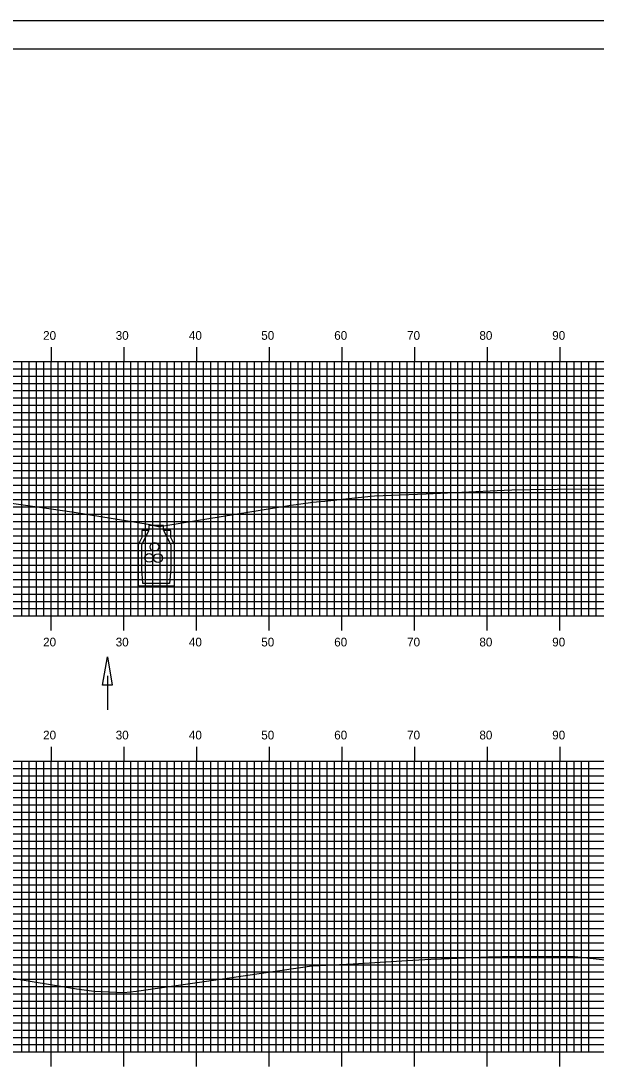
# Model space of a CAD drawing. Extents: x 852320 to 852663, y 366605 to 366825.
# Drawn here: x 852501.3 to 852580.5, y 366680.6 to 366824.9 of the extents above; entities that cross this region are included whole.
import ezdxf

# ---------------------------------------------------------------- set-up
doc = ezdxf.new("R2010")
doc.units = 0
for name, color, linetype in [('BORDER', 7, 'Continuous'), ('D_Drainage_Ditch_Line', 7, 'Continuous'), ('H_V ANNOTATION', 7, 'Continuous'), ('M_Drainage_CB', 7, 'Continuous'), ('M_Roadway_Centerline', 7, 'Continuous'), ('MAJOR', 7, 'Continuous'), ('MINOR', 7, 'Continuous'), ('PLOT BOUNDARY', 7, 'Continuous'), ('S_Drainage_CB', 7, 'Continuous'), ('S_Drainage_Invert', 7, 'Continuous'), ('S_Roadway_Centerline', 7, 'Continuous')]:
    doc.layers.add(name, color=color, linetype=linetype)

msp = doc.modelspace()

# ---------------------------------------------------------------- linework, layer by layer
at = {"layer": 'BORDER'}
msp.add_lwpolyline([(852335.88, 366611.06), (852655.88, 366611.06), (852655.88, 366821.06), (852335.88, 366821.06)], close=True, dxfattribs=at)
at = {"layer": 'D_Drainage_Ditch_Line'}
msp.add_line((852513.23, 366734.83), (852513.23, 366730.13), dxfattribs=at)
msp.add_lwpolyline([(852513.88, 366733.52), (852512.57, 366733.52), (852513.23, 366737.45)], close=True, dxfattribs=at)
at = {"layer": 'M_Drainage_CB'}
for p, q in [((852517.96, 366753.85), (852517.47, 366752.83)), ((852518.95, 366754.83), (852517.96, 366754.83)), ((852517.96, 366754.83), (852517.96, 366753.85)), ((852517.96, 366752.83), (852518.95, 366754.83)), ((852521.97, 366754.83), (852520.95, 366754.83)), ((852520.95, 366754.83), (852521.97, 366752.83)), ((852521.97, 366753.85), (852521.97, 366754.83)), ((852522.46, 366752.83), (852521.97, 366753.85)), ((852517.47, 366752.83), (852517.47, 366747.19)), ((852517.96, 366749.52), (852517.96, 366752.83)), ((852521.97, 366752.83), (852521.97, 366749.52)), ((852522.46, 366747.19), (852522.46, 366752.83)), ((852518.13, 366747.52), (852517.96, 366749.52)), ((852521.97, 366749.52), (852521.8, 366747.52)), ((852517.47, 366747.19), (852522.46, 366747.19)), ((852521.8, 366747.52), (852518.13, 366747.52))]:
    msp.add_line(p, q, dxfattribs=at)
msp.add_lwpolyline([(852521.44, 366754.87), (852520.95, 366754.87), (852520.95, 366755.5), (852518.95, 366755.5), (852518.95, 366754.87), (852518.46, 366754.87)], dxfattribs=at)
at = {"layer": 'MAJOR'}
for p, q in [((852505.48, 366780.06), (852505.48, 366778.06)), ((852515.48, 366780.06), (852515.48, 366778.06)), ((852525.48, 366780.06), (852525.48, 366778.06)), ((852535.48, 366780.06), (852535.48, 366778.06)), ((852545.48, 366780.06), (852545.48, 366778.06)), ((852555.48, 366780.06), (852555.48, 366778.06)), ((852565.48, 366780.06), (852565.48, 366778.06)), ((852575.48, 366780.06), (852575.48, 366778.06)), ((852345.48, 366778.06), (852625.48, 366778.06)), ((852345.48, 366778.06), (852625.48, 366778.06)), ((852505.48, 366743.06), (852505.48, 366778.06)), ((852515.48, 366743.06), (852515.48, 366778.06)), ((852525.48, 366743.06), (852525.48, 366778.06)), ((852535.48, 366743.06), (852535.48, 366778.06)), ((852545.48, 366743.06), (852545.48, 366778.06)), ((852555.48, 366743.06), (852555.48, 366778.06)), ((852565.48, 366743.06), (852565.48, 366778.06)), ((852575.48, 366743.06), (852575.48, 366778.06)), ((852345.48, 366773.06), (852625.48, 366773.06)), ((852345.48, 366768.06), (852625.48, 366768.06)), ((852345.48, 366763.06), (852625.48, 366763.06)), ((852345.48, 366758.06), (852625.48, 366758.06)), ((852345.48, 366753.06), (852625.48, 366753.06)), ((852345.48, 366748.06), (852625.48, 366748.06)), ((852345.48, 366743.06), (852625.48, 366743.06)), ((852345.48, 366743.06), (852625.48, 366743.06)), ((852505.48, 366741.05), (852505.48, 366743.06)), ((852515.48, 366741.05), (852515.48, 366743.06)), ((852525.48, 366741.05), (852525.48, 366743.06)), ((852535.48, 366741.05), (852535.48, 366743.06)), ((852545.48, 366741.05), (852545.48, 366743.06)), ((852555.48, 366741.05), (852555.48, 366743.06)), ((852565.48, 366741.05), (852565.48, 366743.06)), ((852575.48, 366741.05), (852575.48, 366743.06)), ((852505.48, 366725.06), (852505.48, 366723.06)), ((852515.48, 366725.06), (852515.48, 366723.06)), ((852525.48, 366725.06), (852525.48, 366723.06)), ((852535.48, 366725.06), (852535.48, 366723.06)), ((852545.48, 366725.06), (852545.48, 366723.06)), ((852555.48, 366725.06), (852555.48, 366723.06)), ((852565.48, 366725.06), (852565.48, 366723.06)), ((852575.48, 366725.06), (852575.48, 366723.06)), ((852345.48, 366723.06), (852625.48, 366723.06)), ((852345.48, 366723.06), (852625.48, 366723.06)), ((852505.48, 366683.06), (852505.48, 366723.06)), ((852515.48, 366683.06), (852515.48, 366723.06)), ((852525.48, 366683.06), (852525.48, 366723.06)), ((852535.48, 366683.06), (852535.48, 366723.06)), ((852545.48, 366683.06), (852545.48, 366723.06)), ((852555.48, 366683.06), (852555.48, 366723.06)), ((852565.48, 366683.06), (852565.48, 366723.06)), ((852575.48, 366683.06), (852575.48, 366723.06)), ((852345.48, 366718.06), (852625.48, 366718.06)), ((852345.48, 366713.06), (852625.48, 366713.06)), ((852345.48, 366708.06), (852625.48, 366708.06)), ((852345.48, 366703.06), (852625.48, 366703.06)), ((852345.48, 366698.06), (852625.48, 366698.06)), ((852345.48, 366693.06), (852625.48, 366693.06)), ((852345.48, 366688.06), (852625.48, 366688.06)), ((852345.48, 366683.06), (852625.48, 366683.06)), ((852345.48, 366683.06), (852625.48, 366683.06)), ((852505.48, 366681.05), (852505.48, 366683.06)), ((852515.48, 366681.05), (852515.48, 366683.06)), ((852525.48, 366681.05), (852525.48, 366683.06)), ((852535.48, 366681.05), (852535.48, 366683.06)), ((852545.48, 366681.05), (852545.48, 366683.06)), ((852555.48, 366681.05), (852555.48, 366683.06)), ((852565.48, 366681.05), (852565.48, 366683.06)), ((852575.48, 366681.05), (852575.48, 366683.06))]:
    msp.add_line(p, q, dxfattribs=at)
at = {"layer": 'MINOR'}
for p, q in [((852345.48, 366777.06), (852625.48, 366777.06)), ((852501.48, 366743.06), (852501.48, 366778.06)), ((852502.48, 366743.06), (852502.48, 366778.06)), ((852503.48, 366743.06), (852503.48, 366778.06)), ((852504.48, 366743.06), (852504.48, 366778.06)), ((852506.48, 366743.06), (852506.48, 366778.06)), ((852507.48, 366743.06), (852507.48, 366778.06)), ((852508.48, 366743.06), (852508.48, 366778.06)), ((852509.48, 366743.06), (852509.48, 366778.06)), ((852510.48, 366743.06), (852510.48, 366778.06)), ((852511.48, 366743.06), (852511.48, 366778.06)), ((852512.48, 366743.06), (852512.48, 366778.06)), ((852513.48, 366743.06), (852513.48, 366778.06)), ((852514.48, 366743.06), (852514.48, 366778.06)), ((852516.48, 366743.06), (852516.48, 366778.06)), ((852517.48, 366743.06), (852517.48, 366778.06)), ((852518.48, 366743.06), (852518.48, 366778.06)), ((852519.48, 366743.06), (852519.48, 366778.06)), ((852520.48, 366743.06), (852520.48, 366778.06)), ((852521.48, 366743.06), (852521.48, 366778.06)), ((852522.48, 366743.06), (852522.48, 366778.06)), ((852523.48, 366743.06), (852523.48, 366778.06)), ((852524.48, 366743.06), (852524.48, 366778.06)), ((852526.48, 366743.06), (852526.48, 366778.06)), ((852527.48, 366743.06), (852527.48, 366778.06)), ((852528.48, 366743.06), (852528.48, 366778.06)), ((852529.48, 366743.06), (852529.48, 366778.06)), ((852530.48, 366743.06), (852530.48, 366778.06)), ((852531.48, 366743.06), (852531.48, 366778.06)), ((852532.48, 366743.06), (852532.48, 366778.06)), ((852533.48, 366743.06), (852533.48, 366778.06)), ((852534.48, 366743.06), (852534.48, 366778.06)), ((852536.48, 366743.06), (852536.48, 366778.06)), ((852537.48, 366743.06), (852537.48, 366778.06)), ((852538.48, 366743.06), (852538.48, 366778.06)), ((852539.48, 366743.06), (852539.48, 366778.06)), ((852540.48, 366743.06), (852540.48, 366778.06)), ((852541.48, 366743.06), (852541.48, 366778.06)), ((852542.48, 366743.06), (852542.48, 366778.06)), ((852543.48, 366743.06), (852543.48, 366778.06)), ((852544.48, 366743.06), (852544.48, 366778.06)), ((852546.48, 366743.06), (852546.48, 366778.06)), ((852547.48, 366743.06), (852547.48, 366778.06)), ((852548.48, 366743.06), (852548.48, 366778.06)), ((852549.48, 366743.06), (852549.48, 366778.06)), ((852550.48, 366743.06), (852550.48, 366778.06)), ((852551.48, 366743.06), (852551.48, 366778.06)), ((852552.48, 366743.06), (852552.48, 366778.06)), ((852553.48, 366743.06), (852553.48, 366778.06)), ((852554.48, 366743.06), (852554.48, 366778.06)), ((852556.48, 366743.06), (852556.48, 366778.06)), ((852557.48, 366743.06), (852557.48, 366778.06)), ((852558.48, 366743.06), (852558.48, 366778.06)), ((852559.48, 366743.06), (852559.48, 366778.06)), ((852560.48, 366743.06), (852560.48, 366778.06)), ((852561.48, 366743.06), (852561.48, 366778.06)), ((852562.48, 366743.06), (852562.48, 366778.06)), ((852563.48, 366743.06), (852563.48, 366778.06)), ((852564.48, 366743.06), (852564.48, 366778.06)), ((852566.48, 366743.06), (852566.48, 366778.06)), ((852567.48, 366743.06), (852567.48, 366778.06)), ((852568.48, 366743.06), (852568.48, 366778.06)), ((852569.48, 366743.06), (852569.48, 366778.06)), ((852570.48, 366743.06), (852570.48, 366778.06)), ((852571.48, 366743.06), (852571.48, 366778.06)), ((852572.48, 366743.06), (852572.48, 366778.06)), ((852573.48, 366743.06), (852573.48, 366778.06)), ((852574.48, 366743.06), (852574.48, 366778.06)), ((852576.48, 366743.06), (852576.48, 366778.06)), ((852577.48, 366743.06), (852577.48, 366778.06)), ((852578.48, 366743.06), (852578.48, 366778.06)), ((852579.48, 366743.06), (852579.48, 366778.06)), ((852580.48, 366743.06), (852580.48, 366778.06)), ((852345.48, 366776.06), (852625.48, 366776.06)), ((852345.48, 366775.06), (852625.48, 366775.06)), ((852345.48, 366774.06), (852625.48, 366774.06)), ((852345.48, 366772.06), (852625.48, 366772.06)), ((852345.48, 366771.06), (852625.48, 366771.06)), ((852345.48, 366770.06), (852625.48, 366770.06)), ((852345.48, 366769.06), (852625.48, 366769.06)), ((852345.48, 366767.06), (852625.48, 366767.06)), ((852345.48, 366766.06), (852625.48, 366766.06)), ((852345.48, 366765.06), (852625.48, 366765.06)), ((852345.48, 366764.06), (852625.48, 366764.06)), ((852345.48, 366762.06), (852625.48, 366762.06)), ((852345.48, 366761.06), (852625.48, 366761.06)), ((852345.48, 366760.06), (852625.48, 366760.06)), ((852345.48, 366759.06), (852625.48, 366759.06)), ((852345.48, 366757.06), (852625.48, 366757.06)), ((852345.48, 366756.06), (852625.48, 366756.06)), ((852345.48, 366755.06), (852625.48, 366755.06)), ((852345.48, 366754.06), (852625.48, 366754.06)), ((852345.48, 366752.06), (852625.48, 366752.06)), ((852345.48, 366751.06), (852625.48, 366751.06)), ((852345.48, 366750.06), (852625.48, 366750.06)), ((852345.48, 366749.06), (852625.48, 366749.06)), ((852345.48, 366747.06), (852625.48, 366747.06)), ((852345.48, 366746.06), (852625.48, 366746.06)), ((852345.48, 366745.06), (852625.48, 366745.06)), ((852345.48, 366744.06), (852625.48, 366744.06)), ((852345.48, 366722.06), (852625.48, 366722.06)), ((852501.48, 366683.06), (852501.48, 366723.06)), ((852502.48, 366683.06), (852502.48, 366723.06)), ((852503.48, 366683.06), (852503.48, 366723.06)), ((852504.48, 366683.06), (852504.48, 366723.06)), ((852506.48, 366683.06), (852506.48, 366723.06)), ((852507.48, 366683.06), (852507.48, 366723.06)), ((852508.48, 366683.06), (852508.48, 366723.06)), ((852509.48, 366683.06), (852509.48, 366723.06)), ((852510.48, 366683.06), (852510.48, 366723.06)), ((852511.48, 366683.06), (852511.48, 366723.06)), ((852512.48, 366683.06), (852512.48, 366723.06)), ((852513.48, 366683.06), (852513.48, 366723.06)), ((852514.48, 366683.06), (852514.48, 366723.06)), ((852516.48, 366683.06), (852516.48, 366723.06)), ((852517.48, 366683.06), (852517.48, 366723.06)), ((852518.48, 366683.06), (852518.48, 366723.06)), ((852519.48, 366683.06), (852519.48, 366723.06)), ((852520.48, 366683.06), (852520.48, 366723.06)), ((852521.48, 366683.06), (852521.48, 366723.06)), ((852522.48, 366683.06), (852522.48, 366723.06)), ((852523.48, 366683.06), (852523.48, 366723.06)), ((852524.48, 366683.06), (852524.48, 366723.06)), ((852526.48, 366683.06), (852526.48, 366723.06)), ((852527.48, 366683.06), (852527.48, 366723.06)), ((852528.48, 366683.06), (852528.48, 366723.06)), ((852529.48, 366683.06), (852529.48, 366723.06)), ((852530.48, 366683.06), (852530.48, 366723.06)), ((852531.48, 366683.06), (852531.48, 366723.06)), ((852532.48, 366683.06), (852532.48, 366723.06)), ((852533.48, 366683.06), (852533.48, 366723.06)), ((852534.48, 366683.06), (852534.48, 366723.06)), ((852536.48, 366683.06), (852536.48, 366723.06)), ((852537.48, 366683.06), (852537.48, 366723.06)), ((852538.48, 366683.06), (852538.48, 366723.06)), ((852539.48, 366683.06), (852539.48, 366723.06)), ((852540.48, 366683.06), (852540.48, 366723.06)), ((852541.48, 366683.06), (852541.48, 366723.06)), ((852542.48, 366683.06), (852542.48, 366723.06)), ((852543.48, 366683.06), (852543.48, 366723.06)), ((852544.48, 366683.06), (852544.48, 366723.06)), ((852546.48, 366683.06), (852546.48, 366723.06)), ((852547.48, 366683.06), (852547.48, 366723.06)), ((852548.48, 366683.06), (852548.48, 366723.06)), ((852549.48, 366683.06), (852549.48, 366723.06)), ((852550.48, 366683.06), (852550.48, 366723.06)), ((852551.48, 366683.06), (852551.48, 366723.06)), ((852552.48, 366683.06), (852552.48, 366723.06)), ((852553.48, 366683.06), (852553.48, 366723.06)), ((852554.48, 366683.06), (852554.48, 366723.06)), ((852556.48, 366683.06), (852556.48, 366723.06)), ((852557.48, 366683.06), (852557.48, 366723.06)), ((852558.48, 366683.06), (852558.48, 366723.06)), ((852559.48, 366683.06), (852559.48, 366723.06)), ((852560.48, 366683.06), (852560.48, 366723.06)), ((852561.48, 366683.06), (852561.48, 366723.06)), ((852562.48, 366683.06), (852562.48, 366723.06)), ((852563.48, 366683.06), (852563.48, 366723.06)), ((852564.48, 366683.06), (852564.48, 366723.06)), ((852566.48, 366683.06), (852566.48, 366723.06)), ((852567.48, 366683.06), (852567.48, 366723.06)), ((852568.48, 366683.06), (852568.48, 366723.06)), ((852569.48, 366683.06), (852569.48, 366723.06)), ((852570.48, 366683.06), (852570.48, 366723.06)), ((852571.48, 366683.06), (852571.48, 366723.06)), ((852572.48, 366683.06), (852572.48, 366723.06)), ((852573.48, 366683.06), (852573.48, 366723.06)), ((852574.48, 366683.06), (852574.48, 366723.06)), ((852576.48, 366683.06), (852576.48, 366723.06)), ((852577.48, 366683.06), (852577.48, 366723.06)), ((852578.48, 366683.06), (852578.48, 366723.06)), ((852579.48, 366683.06), (852579.48, 366723.06)), ((852345.48, 366721.06), (852625.48, 366721.06)), ((852345.48, 366720.06), (852625.48, 366720.06)), ((852345.48, 366719.06), (852625.48, 366719.06)), ((852345.48, 366717.06), (852625.48, 366717.06)), ((852345.48, 366716.06), (852625.48, 366716.06)), ((852345.48, 366715.06), (852625.48, 366715.06)), ((852345.48, 366714.06), (852625.48, 366714.06)), ((852345.48, 366712.06), (852625.48, 366712.06)), ((852345.48, 366711.06), (852625.48, 366711.06)), ((852345.48, 366710.06), (852625.48, 366710.06)), ((852345.48, 366709.06), (852625.48, 366709.06)), ((852345.48, 366707.06), (852625.48, 366707.06)), ((852345.48, 366706.06), (852625.48, 366706.06)), ((852345.48, 366705.06), (852625.48, 366705.06)), ((852345.48, 366704.06), (852625.48, 366704.06)), ((852345.48, 366702.06), (852625.48, 366702.06)), ((852345.48, 366701.06), (852625.48, 366701.06)), ((852345.48, 366700.06), (852625.48, 366700.06)), ((852345.48, 366699.06), (852625.48, 366699.06)), ((852345.48, 366697.06), (852625.48, 366697.06)), ((852345.48, 366696.06), (852625.48, 366696.06)), ((852345.48, 366695.06), (852625.48, 366695.06)), ((852345.48, 366694.06), (852625.48, 366694.06)), ((852345.48, 366692.06), (852625.48, 366692.06)), ((852345.48, 366691.06), (852625.48, 366691.06)), ((852345.48, 366690.06), (852625.48, 366690.06)), ((852345.48, 366689.06), (852625.48, 366689.06)), ((852345.48, 366687.06), (852625.48, 366687.06)), ((852345.48, 366686.06), (852625.48, 366686.06)), ((852345.48, 366685.06), (852625.48, 366685.06)), ((852345.48, 366684.06), (852625.48, 366684.06))]:
    msp.add_line(p, q, dxfattribs=at)
at = {"layer": 'PLOT BOUNDARY'}
msp.add_lwpolyline([(852319.69, 366604.94), (852659.69, 366604.94), (852659.69, 366824.94), (852319.69, 366824.94)], close=True, dxfattribs=at)
at = {"layer": 'S_Drainage_CB'}
for p, q in [((852517.96, 366753.85), (852517.47, 366752.83)), ((852518.95, 366754.83), (852517.96, 366754.83)), ((852517.96, 366754.83), (852517.96, 366753.85)), ((852517.96, 366752.83), (852518.95, 366754.83)), ((852521.97, 366754.83), (852520.95, 366754.83)), ((852520.95, 366754.83), (852521.97, 366752.83)), ((852521.97, 366753.85), (852521.97, 366754.83)), ((852522.46, 366752.83), (852521.97, 366753.85)), ((852517.47, 366752.83), (852517.47, 366747.19)), ((852517.96, 366749.52), (852517.96, 366752.83)), ((852521.97, 366752.83), (852521.97, 366749.52)), ((852522.46, 366747.19), (852522.46, 366752.83)), ((852518.13, 366747.52), (852517.96, 366749.52)), ((852521.97, 366749.52), (852521.8, 366747.52)), ((852517.47, 366747.19), (852522.46, 366747.19)), ((852521.8, 366747.52), (852518.13, 366747.52))]:
    msp.add_line(p, q, dxfattribs=at)
msp.add_lwpolyline([(852521.44, 366754.87), (852520.95, 366754.87), (852520.95, 366755.5), (852518.95, 366755.5), (852518.95, 366754.87), (852518.46, 366754.87)], dxfattribs=at)
at = {"layer": 'S_Drainage_Invert'}
for centre in [(852519.7, 366752.55), (852518.98, 366751.04), (852520.2, 366751.02)]:
    msp.add_circle(centre, 0.6, dxfattribs=at)
at = {"layer": 'S_Roadway_Centerline'}
for points in [[(852494.25, 366759.39), (852504.54, 366757.92), (852508.65, 366757.32), (852519.11, 366755.62), (852520.23, 366755.38), (852520.34, 366755.37), (852521.57, 366755.56), (852538.2, 366758.24), (852541.49, 366758.71), (852542, 366758.75), (852543.16, 366758.87), (852547.28, 366759.29), (852550.01, 366759.57), (852553.54, 366759.71), (852557.11, 366759.85), (852562.02, 366760.1), (852567.83, 366760.35), (852568.88, 366760.39), (852571.41, 366760.44), (852578.84, 366760.53), (852591.8, 366760.52)], [(852489.87, 366694.9), (852508.97, 366691.72), (852511.43, 366691.42), (852515.47, 366691.25), (852515.5, 366691.24), (852517.22, 366691.43), (852527.2, 366692.82), (852536.97, 366694.26), (852541.38, 366694.89), (852544.28, 366695.04), (852547.06, 366695.16), (852555.26, 366695.66), (852557.75, 366695.83), (852559.23, 366695.86), (852565.67, 366696.15), (852569.48, 366696.24), (852577.58, 366696.2), (852582.17, 366695.66)]]:
    msp.add_lwpolyline(points, dxfattribs=at)

# ---------------------------------------------------------------- texts
at = {"layer": 'H_V ANNOTATION'}
for s, p in [('20', (852504.39, 366781.06)), ('30', (852514.38, 366781.06)), ('40', (852524.45, 366781.06)), ('50', (852534.41, 366781.06)), ('60', (852544.45, 366781.06)), ('70', (852554.48, 366781.06)), ('80', (852564.43, 366781.06)), ('90', (852574.45, 366781.06)), ('20', (852504.39, 366738.86)), ('30', (852514.38, 366738.86)), ('40', (852524.45, 366738.86)), ('50', (852534.41, 366738.86)), ('60', (852544.45, 366738.86)), ('70', (852554.48, 366738.86)), ('80', (852564.43, 366738.86)), ('90', (852574.45, 366738.86)), ('20', (852504.39, 366726.06)), ('30', (852514.38, 366726.06)), ('40', (852524.45, 366726.06)), ('50', (852534.41, 366726.06)), ('60', (852544.45, 366726.06)), ('70', (852554.48, 366726.06)), ('80', (852564.43, 366726.06)), ('90', (852574.45, 366726.06))]:
    msp.add_text(s, height=1.2, dxfattribs=at).set_placement(p)
at = {"layer": 'M_Roadway_Centerline'}
for s, p in [('C', (852557.75, 366695.83)), ('L', (852557.75, 366695.82))]:
    msp.add_text(s, height=0.0146, dxfattribs=at).set_placement(p)

doc.saveas('drawing.dxf')
